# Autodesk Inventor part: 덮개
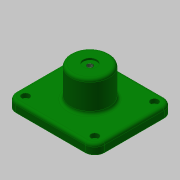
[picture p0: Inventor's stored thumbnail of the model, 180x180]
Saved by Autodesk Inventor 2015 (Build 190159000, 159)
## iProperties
Created: 2017-08
Part Number: 덮개
Material: 알루미늄 6061
Document SubType Name: Modeling
Designer: mduedu
Density: 1 g/cm^3
Appearance: 진녹색
Author: mduedu
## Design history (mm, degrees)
sketch "스케치1"
  geometry: L1 (46, -41)-(-46, -41); L2 (-46, -41)-(-46, 41); L3 (-46, 41)-(46, 41); L4 (46, 41)-(46, -41); 1 further point
  constraints: 8 end point, 2 parallel, 1 horizontal, 1 perpendicular
  dimensions: "d0" = 92 distance of L2.end L3.end; "d2" = 82 distance of L1.end L2.end; "d3" = 41 distance from line of L3 point (0, 0) (= 0.5 x d2); "d4" = 46 distance from line of point (0, 0) L4 (= 0.5 x d0)
extrude "돌출1" new body sketch "스케치1" distance "d5" = 10; taper "d6" = 0 deg
sketch "스케치2"
  geometry: C1 r 20 at (0, 0); 1 further point
  constraints: 1 centre point, 1 coincident
  dimensions: "d55" = 40 diameter of C1
extrude "돌출2" join sketch "스케치2" distance "d9" = 32; taper "d10" = 0 deg
sketch "스케치3"
  geometry: L1 (-26, -26)-(26, -26); L2 (26, -26)-(26, 26); L3 (26, 26)-(-26, 26); L4 (-26, 26)-(-26, -26); L5 (-26, -26)-(26, 26); L6 (26, -26)-(-26, 26); 1 further point
  constraints: 12 end point, 2 midpoint, 2 parallel, 2 perpendicular, 1 horizontal
  dimensions: "d11" = 52 distance of L3.end L2.end
extrude "돌출3" join sketch "스케치3" distance "d12" = 6; taper "d13" = 0 deg
sketch "스케치4"
  geometry: L1 (-17, -17)-(17, -17); L2 (17, -17)-(17, 17); L3 (17, 17)-(-17, 17); L4 (-17, 17)-(-17, -17); L5 (-17, -17)-(17, 17); L6 (17, -17)-(-17, 17); 1 further point
  constraints: 12 end point, 2 midpoint, 2 parallel, 2 perpendicular, 1 horizontal
  dimensions: "d14" = 34 distance of L2.end L3.end
extrude "돌출4" cut sketch "스케치4" distance "d16" = 5; taper "d17" = 0 deg
sketch "스케치5"
  geometry: C1 r 9 at (0, 0); 1 further point
  constraints: 1 centre point, 1 coincident
  dimensions: "d18" = 18 diameter of C1
extrude "돌출5" cut sketch "스케치5" distance "d19" = 34; taper "d20" = 0 deg
sketch "스케치6"
  geometry: 2 further points
  constraints: 1 coincident
hole "구멍1" sketch "스케치6" at (0, 0) diameter "d21" = 5.917; stored, may be unused: countersink angle "d25" = 90 deg, drill point angle "d27" = 118 deg; dims "d22" = 6, "d23" = 14, "d24" = 2, "d26" = 8
fillet "모깎기1" dims "d36" = 10
fillet "모깎기3" dims "d38" = 3
fillet "모깎기4" dims "d39" = 3
fillet "모깎기5" dims "d40" = 3
chamfer "모따기1" distance "d41" = 1; stored, may be unused: second distance "d42" = 2, angle "d43" = 45 deg
fillet "모깎기6" dims "d44" = 3
fillet "모깎기7" dims "d45" = 3
fillet "모깎기8" dims "d46" = 3
sketch "스케치8"
  geometry: A1 r 10 centre (-36, -31) between (-46, -31) and (-36, -41) reference; A2 r 10 centre (-36, 31) between (-36, 41) and (-46, 31) reference; A3 r 10 centre (36, 31) between (46, 31) and (36, 41) reference; A4 r 10 centre (36, -31) between (36, -41) and (46, -31) reference; 5 further points
  constraints: 4 coincident
sketch "스케치9"
  geometry: 4 further points
  constraints: 4 other
hole "구멍3" sketch "스케치9" at (-36, -31), (-36, 31), (36, 31), (36, -31) diameter "d48" = 4.5; stored, may be unused: countersink angle "d52" = 90 deg, drill point angle "d54" = 0 deg; dims "d49" = 6, "d50" = 8, "d51" = 4.6, "d53" = 8
node "솔리드1"
